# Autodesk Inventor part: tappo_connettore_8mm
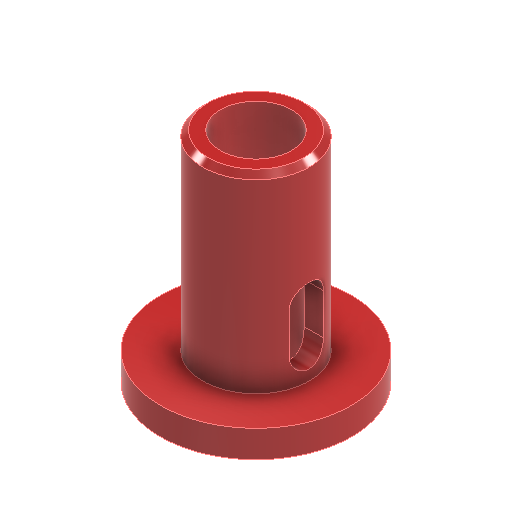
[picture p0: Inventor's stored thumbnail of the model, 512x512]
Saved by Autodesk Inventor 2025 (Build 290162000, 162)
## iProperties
Created: 2025-04
Part Number: tappo_connettore_8mm
Material: Plastica PET
Document SubType Name: Modeling
Designer: R5800u
Density: 1.541 g/cm^3
Appearance: Rosso
Author: R5800u
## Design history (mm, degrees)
sketch "Schizzo1"
  geometry: L1 (0, 0)-(7, 0); L2 (7, 0)-(7, 2); L3 (7, 2)-(3.9, 2); L4 (3.9, 2)-(3.9, 16); L5 (3.9, 16)-(0, 16); L6 (0, 16)-(0, 0); L7 (2.6, 16)-(2.6, 0)
  constraints: 14 end point, 5 perpendicular, 2 point on line, 1 horizontal, 1 vertical
  dimensions: "d0" = 7 distance of L1.start L1.end; "d1" = 2 distance of L1.end L2.end; "d2" = 14 distance of L3.end L4.end; "d3" = 3.9 distance between parallel lines of L6 L4; "d4" = 2.6 distance between parallel lines of L6 L7
revolve "Rivoluzione1" sketch "Schizzo1" stored, may be unused: angle "d5" = 90 deg
chamfer "Smusso1" distance "d6" = 0.4; stored, may be unused: second distance "d7" = 2, angle "d8" = 45 deg
sketch "Schizzo2"
  geometry: L1 (4.025, 0)-(7.025, 0); L2 (4.025, -1.25)-(7.025, -1.25); L3 (7.025, 1.25)-(4.025, 1.25); A1 r 1.25 centre (4.025, 0) between (4.025, 1.25) and (4.025, -1.25); A2 r 1.25 centre (7.025, 0) between (7.025, -1.25) and (7.025, 1.25); 2 further points
  constraints: 8 end point, 4 point on circle, 4 tangent, 2 centre point, 1 horizontal, 1 midpoint, 1 parallel
  dimensions: "d9" = 2.5 diameter of A2; "d12" = 3 distance of L3.start L3.end
extrude "Estrusione1" cut sketch "Schizzo2" stored distance "d10" = 10; taper "d11" = 0 deg
node "Solido1"
